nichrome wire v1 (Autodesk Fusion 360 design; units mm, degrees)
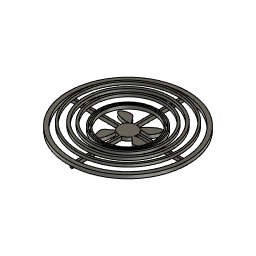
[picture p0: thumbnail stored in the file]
sketch "Sketch1" plane through (0, 0, 0) normal (0, 0, 1) x axis (1, 0, 0)
  curve K1 (6.0577, 10.9616) -> (6.0577, 10.9616)
  curve K2 (6.0577, 10.9616) -> (6.0577, 10.9616)
  curve K3 (6.0577, 10.9616) -> (6.0577, 10.9616)
  curve K4 (10.9382, -3.5735) -> (10.9382, -3.5735)
  curve K5 (10.9382, -3.5735) -> (10.9382, -3.5735)
  curve K6 (10.9382, -3.5735) -> (10.9382, -3.5735)
  curve K7 (-7.1676, 10.1341) -> (-7.1676, 10.1341)
  curve K8 (-7.1676, 10.1341) -> (-7.1676, 10.1341)
  curve K9 (-7.1676, 10.1341) -> (-7.1676, 10.1341)
  curve K10 (-7.2895, -9.5589) -> (-7.2895, -9.5589)
  curve K11 (-7.2895, -9.5589) -> (-7.2895, -9.5589)
  curve K12 (-7.2895, -9.5589) -> (-7.2895, -9.5589)
  circle C1 centre (0, 0) radius 12.5241
  point P1 (0, 0)
  point P2 (0, 0)
  point P4 (0, 0)
  point P5 (6.0577, 10.9616)
  coincident P1 P2
  coincident P1 P4
  coincident C1 P5
extrude "Extrude1" new body sketch "Sketch1" along normal blind 5
sketch "Sketch2" plane through (0, 0, 5) normal (0, 0, 1) x axis (-1, 0, 0)
  curve K1 (7.8082, -9.7921) -> (6.8465, -10.4871)
  curve K2 (6.8517, 10.4837) -> (8.5607, 9.1416)
  curve K3 (-12.2106, 2.7847) -> (-11.2008, 5.6031)
  curve K4 (-6.0577, -10.9616) -> (-8.1749, -9.4882)
  arc A1 centre (0, 0) radius 12.5241 clockwise from (6.8465, -10.4871) to (-6.0577, -10.9616)
  arc A2 centre (0, 0) radius 12.5241 clockwise from (8.5607, 9.1416) to (7.8082, -9.7921)
  arc A3 centre (0, 0) radius 12.5241 clockwise from (-11.2008, 5.6031) to (6.8517, 10.4837)
  arc A4 centre (0, 0) radius 12.5241 clockwise from (-8.1749, -9.4882) to (-12.2106, 2.7847)
  circle C1 centre (0, 0) radius 40.3113
  circle C2 centre (0, 0) radius 38.6887
  circle C3 centre (0, 0) radius 42.0472
  circle C4 centre (0, 0) radius 36.7361
  point P1 (0, 0)
  point P11 (0, 0)
  point P14 (0, 0)
  coincident P1 P11
  concentric C1 C2
  concentric C2 C3
  coincident P1 P14
extrude "Extrude2" new body sketch "Sketch2" profile of C1 C3 along normal blind 5
sketch "Sketch3" plane through (0, 0, 5) normal (0, 0, 1) x axis (-1, 0, 0)
  curve K1 (7.8082, -9.7921) -> (6.8465, -10.4871)
  curve K2 (6.8517, 10.4837) -> (8.5607, 9.1416)
  curve K3 (-12.2106, 2.7847) -> (-11.2008, 5.6031)
  curve K4 (-6.0577, -10.9616) -> (-8.1749, -9.4882)
  arc A1 centre (0, 0) radius 12.5241 clockwise from (6.8465, -10.4871) to (-6.0577, -10.9616)
  arc A2 centre (0, 0) radius 12.5241 clockwise from (8.5607, 9.1416) to (7.8082, -9.7921)
  arc A3 centre (0, 0) radius 12.5241 clockwise from (-11.2008, 5.6031) to (6.8517, 10.4837)
  arc A4 centre (0, 0) radius 12.5241 clockwise from (-8.1749, -9.4882) to (-12.2106, 2.7847)
  circle C1 centre (0, 0) radius 38.5442
  circle C2 centre (0, 0) radius 36.8118
  point P1 (0, 0)
  point P11 (0, 0)
  point P12 (0, 0)
  coincident P1 P11
  coincident P1 P12
extrude "Extrude3" new body sketch "Sketch3" profile of C1 C2 along normal blind 5
sketch "Sketch4" plane through (0, 0, 10) normal (0, 0, 1) x axis (-1, 0, 0)
  line L1 (-79.5893, -78.0883) -> (80.4107, -78.0883)
  line L2 (-79.5893, 81.9117) -> (-79.5893, -78.0883)
  line L3 (80.4107, 81.9117) -> (-79.5893, 81.9117)
  line L4 (80.4107, -78.0883) -> (80.4107, 81.9117)
  circle C1 centre (0, 0) radius 36.8118
  circle C2 centre (0, 0) radius 38.5442
  circle C3 centre (0, 0) radius 52.582
  circle C4 centre (0, 0) radius 49.7551
  circle C5 centre (0, 0) radius 61.9417
  circle C6 centre (0, 0) radius 58.3666
  circle C7 centre (0, 0) radius 73.4024
  circle C8 centre (0, 0) radius 70.7107
  point P1 (0, 0)
  point P9 (0, 0)
  point P10 (0, 0)
  point P3 (80.4107, -78.0883)
  point P4 (-79.5893, -78.0883)
  point P6 (80.4107, 81.9117)
  horizontal L1
  vertical L2
  horizontal L3
  vertical L4
  concentric C1 C3
  concentric C3 C4
  coincident P1 P9
  coincident P1 P10
  concentric C3 C7
  concentric C3 C8
  dimension "d9" distance P3 P4 = 160
  dimension "d10" distance P3 P6 = 160
extrude "Extrude4" new body sketch "Sketch4" profile of C3 C4 C5 C6 C7 C8 along normal blind 5
sketch "Sketch5" plane through (0, 0, 5) normal (0, 0, 1) x axis (-1, 0, 0)
  curve K1 (7.8082, -9.7921) -> (6.8465, -10.4871)
  curve K2 (6.8517, 10.4837) -> (8.5607, 9.1416)
  curve K3 (-12.2106, 2.7847) -> (-11.2008, 5.6031)
  curve K4 (-6.0577, -10.9616) -> (-8.1749, -9.4882)
  arc A1 centre (0, 0) radius 12.5241 clockwise from (6.8465, -10.4871) to (-6.0577, -10.9616)
  arc A2 centre (0, 0) radius 12.5241 clockwise from (8.5607, 9.1416) to (7.8082, -9.7921)
  arc A3 centre (0, 0) radius 12.5241 clockwise from (-11.2008, 5.6031) to (6.8517, 10.4837)
  arc A4 centre (0, 0) radius 12.5241 clockwise from (-8.1749, -9.4882) to (-12.2106, 2.7847)
  circle C1 centre (0, 0) radius 80
  circle C2 centre (0, 0) radius 85.3902
  point P1 (0, 0)
  point P11 (0, 0)
  coincident P1 P11
  concentric C1 C2
  dimension "d13" diameter C1 = 160
extrude "Extrude5" new body sketch "Sketch5" profile of C1 C2 along normal blind 5
sketch "Sketch6" plane through (0, 0, 0) normal (0, 0, 1) x axis (1, 0, 0)
  line L1 (-0.0367, 11.7312) -> (-3.0367, 11.7312)
  line L2 (-0.0367, 81.7312) -> (-0.0367, 11.7312)
  line L3 (-3.0367, 81.7312) -> (-0.0367, 81.7312)
  line L4 (-3.0367, 11.7312) -> (-3.0367, 81.7312)
  line L5 (80, 4.7468) -> (8.1991, 4.7468)
  line L6 (80, 1.7468) -> (80, 4.7468)
  line L7 (8.1991, 1.7468) -> (80, 1.7468)
  line L8 (8.1991, 4.7468) -> (8.1991, 1.7468)
  line L9 (-82.2947, 1.7468) -> (-11.8432, 1.7468)
  line L10 (-82.2947, -1.2532) -> (-82.2947, 1.7468)
  line L11 (-11.8432, -1.2532) -> (-82.2947, -1.2532)
  line L12 (-11.8432, 1.7468) -> (-11.8432, -1.2532)
  line L13 (3, -10) -> (0, -10)
  line L14 (3, -82.7103) -> (3, -10)
  line L15 (0, -82.7103) -> (3, -82.7103)
  line L16 (0, -10) -> (0, -82.7103)
  point P2 (-3.0367, 11.7312)
  point P3 (-0.0367, 11.7312)
  point P5 (-3.0367, 81.7312)
  point P6 (8.1991, 4.7468)
  point P9 (8.1991, 1.7468)
  point P10 (-11.8432, 1.7468)
  point P13 (-11.8432, -1.2532)
  point P14 (0, -10)
  point P15 (3, -10)
  horizontal L1
  vertical L2
  horizontal L3
  vertical L4
  horizontal L5
  vertical L6
  horizontal L7
  vertical L8
  horizontal L9
  vertical L10
  horizontal L11
  vertical L12
  horizontal L13
  vertical L14
  horizontal L15
  vertical L16
  dimension "d16" distance P2 P3 = 3
  dimension "d17" distance P2 P5 = 70
  dimension "d18" distance P6 P9 = 3
  dimension "d19" distance P10 P13 = 3
  dimension "d20" distance P14 P15 = 3
extrude "Extrude6" add sketch "Sketch6" along normal blind 5
sketch "Sketch7" plane through (0, 0, 10) normal (0, 0, 1) x axis (-1, 0, 0)
  curve K1 (5.1073, -102.997) -> (5.1073, -102.997)
  circle C1 centre (0, 0) radius 36.8118
  circle C2 centre (0, 0) radius 38.5442
extrude "Extrude7" cut sketch "Sketch7" profile of C2 K1 along normal blind 1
